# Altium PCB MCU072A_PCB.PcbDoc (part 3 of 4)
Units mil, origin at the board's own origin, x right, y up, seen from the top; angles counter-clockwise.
Board outline 2661.1 x 1953.35 mil, 8 copper layers (Top Layer, Mid-Layer 2, Mid-Layer 3, Mid-Layer 4, Mid-Layer 5, Mid-Layer 6, Mid-Layer 7, Bottom Layer), stack 61.2 mil thick; 186 components, 165 nets, 716 pads, 419 vias.
Unrouted connection lines stored in the file: 1.
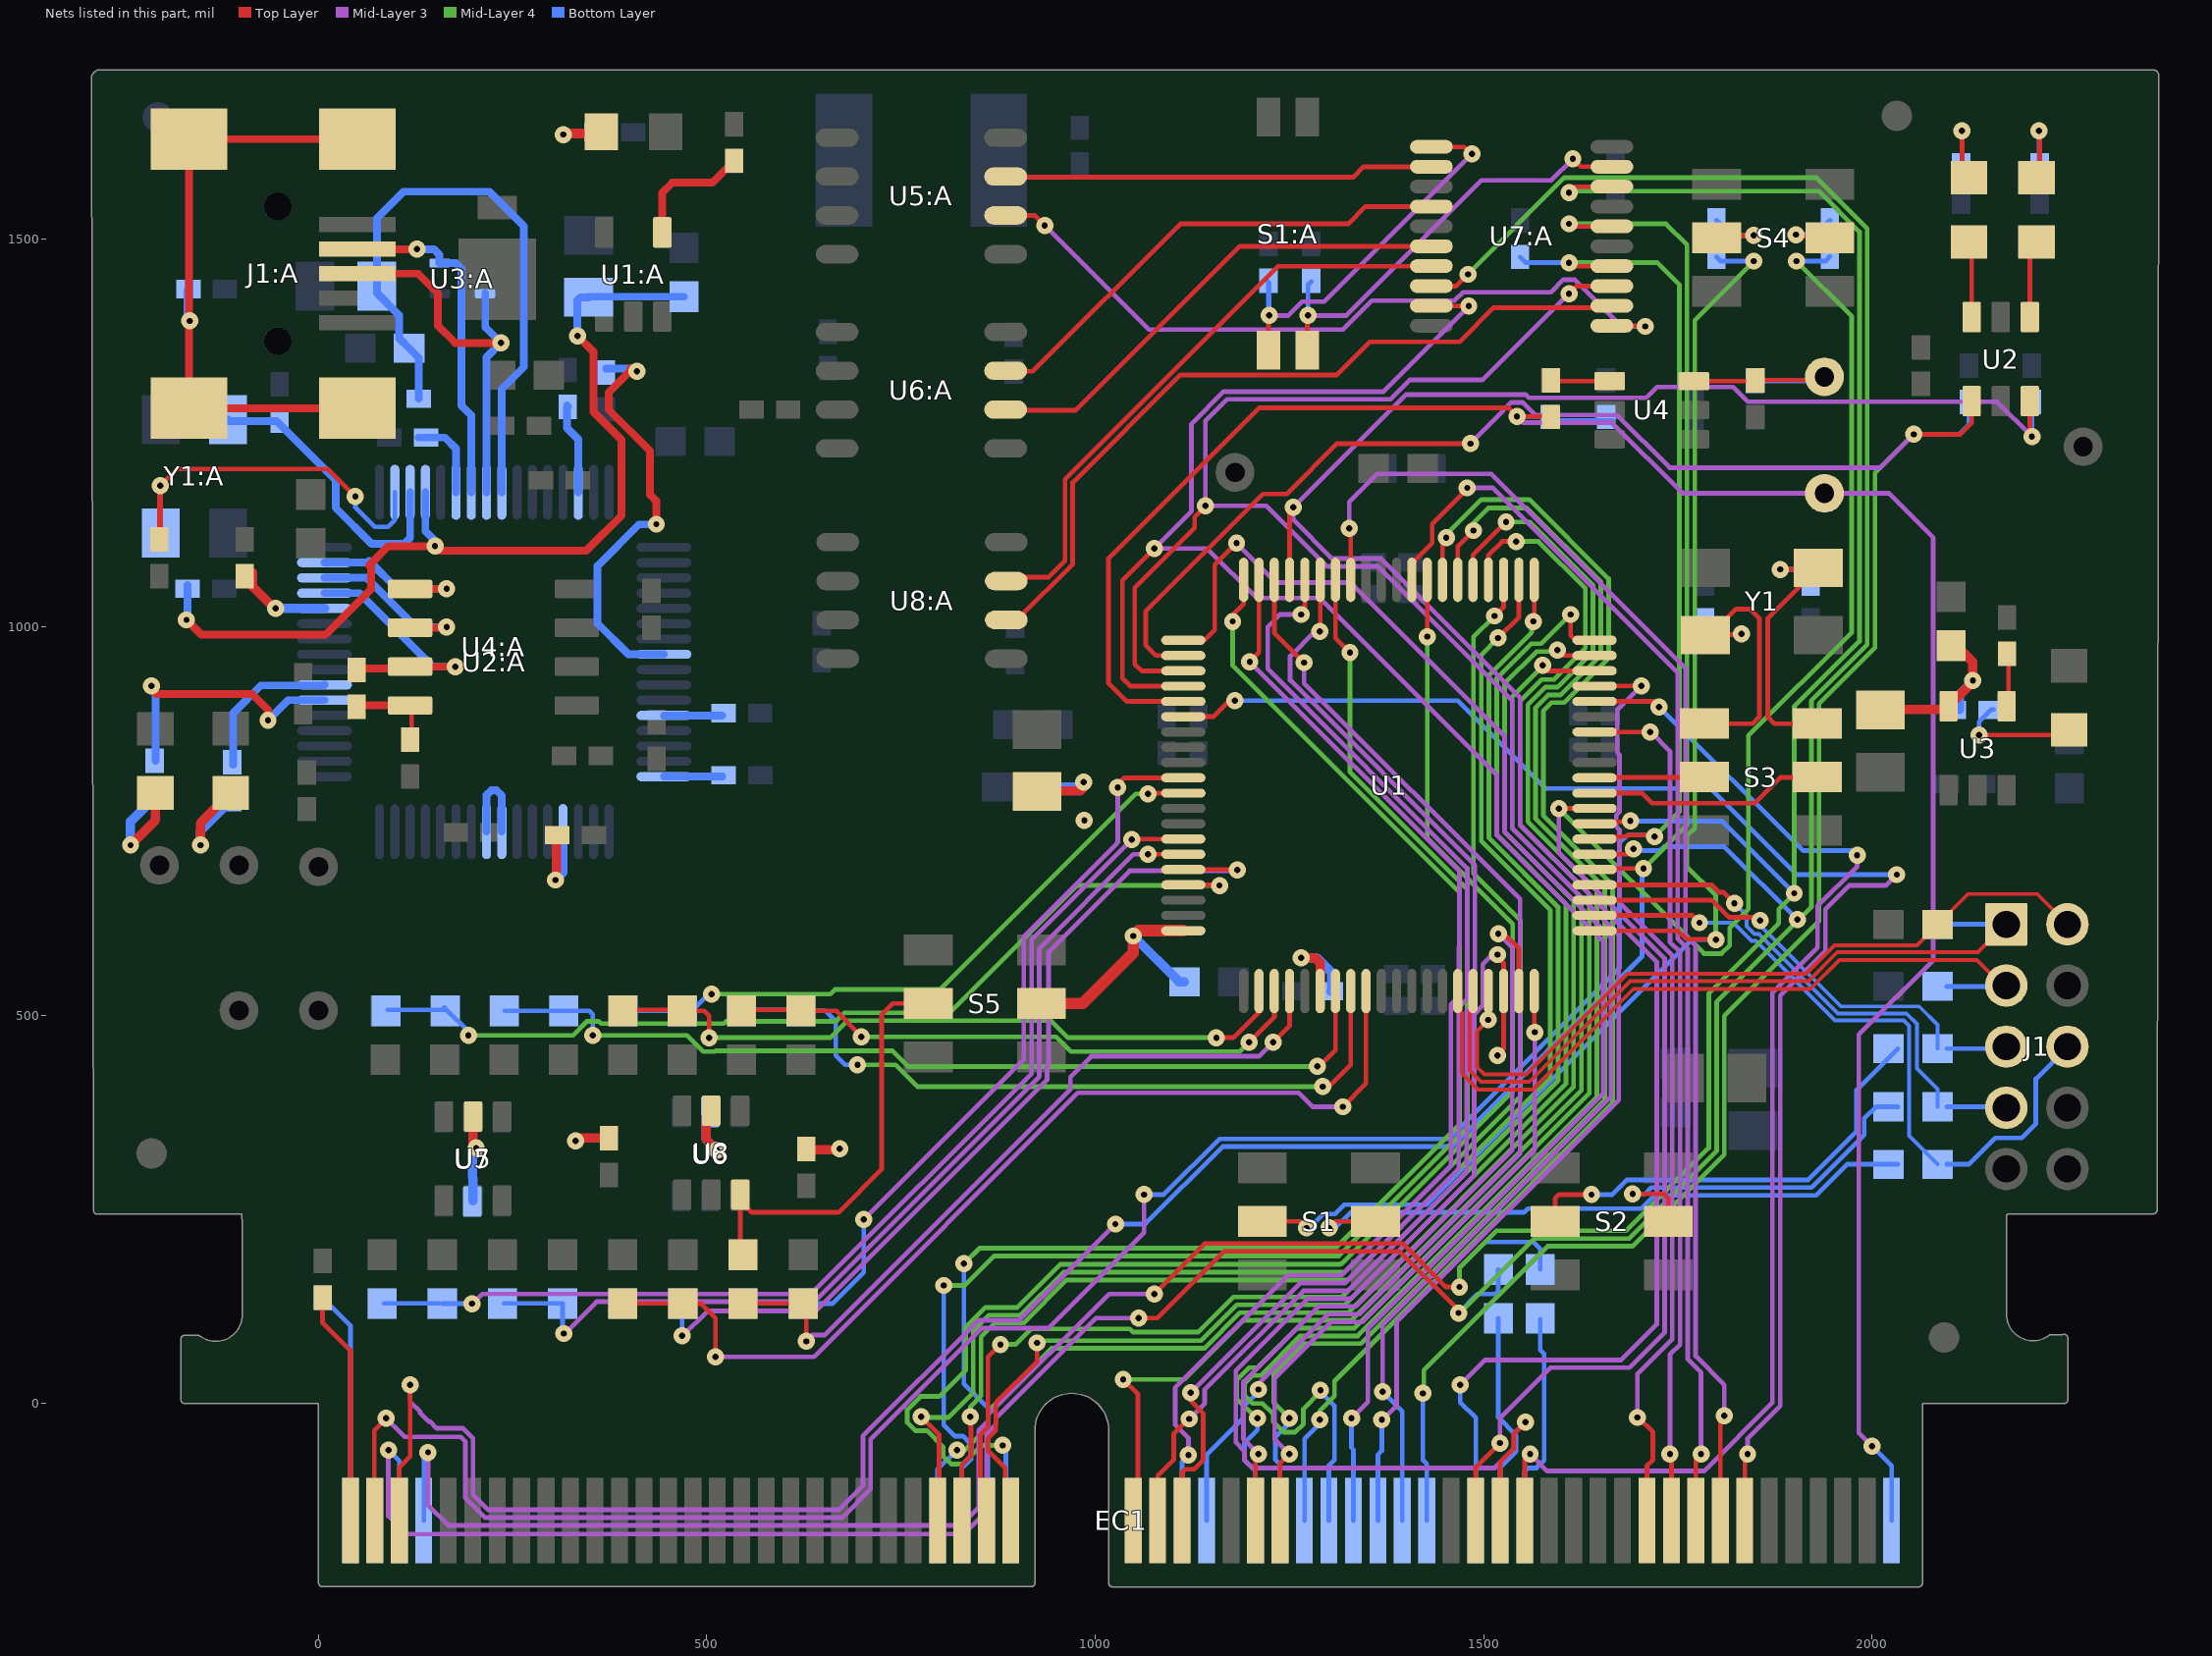
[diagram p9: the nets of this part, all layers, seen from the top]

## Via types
v1: diameter 22, hole 8, Top Layer to Bottom Layer, tented both sides, 419 vias

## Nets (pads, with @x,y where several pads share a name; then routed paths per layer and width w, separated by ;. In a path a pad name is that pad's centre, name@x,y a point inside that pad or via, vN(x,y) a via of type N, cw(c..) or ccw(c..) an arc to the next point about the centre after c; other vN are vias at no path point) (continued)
MCU_A4/C14: C33.1 R27.1 U1.27 | length 1200.8
  Top Layer w6: v1(1286,434) 1288.5,434 1309.31,454.81 U1.27@1309.31,531
  Mid-Layer 4 w6: v1(353,474) 474.54,474 495.54,453 510.46,453 511.46,454 739.14,454 759.14,434 v1(1286,434)
  Bottom Layer w6: R27.1@239.57,505.5 C33.1@315.86,505.5 348.5,505.5 353,501 v1(353,474)
MCU_A5/C2: C34.1 R28.1 U1.17 | length 1221
  Top Layer w6: U1.17@1113.45,667.81 1159.19,667.81 v1(1160,667)
  Mid-Layer 4 w6: v1(193,474) 327.54,474 345.54,492 360.72,492 363.72,489 517.74,489 521.74,489 524.74,492 666.14,492 677.14,503 812.43,503 976.43,667 v1(1160,667)
  Bottom Layer w6: C34.1@89.1,506.9 163.9,506.9 R28.1@164.4,507.4 ; R28.1@162,509.79 R28.1@164.4,507.4 ; R28.1@164.79,507 R28.1@164.4,507.4 ; v1(193,474) 193,478.79 R28.1@164.4,507.4
MCU_A6: C35.1 R29.1 U1.10 | length 1030.8
  Top Layer w6: v1(1029,793) 1029,795 1028,796 1026,794 1037.61,805.61 U1.10@1113.45,805.61
  Mid-Layer 3 w6: v1(702,237) 908,443 908,601.32 1026,719.32 1029,722.32 v1(1029,793)
  Bottom Layer w6: R29.1@539.1,128.9 C35.1@617.1,128.9 ; C35.1@623.93,128.5 661.5,128.5 702,169 v1(702,237)
MCU_A7/C3: C36.1 R30.1 U1.23 | length 759.8
  Top Layer w6: R30.1@539.1,506.9 C36.1@615.1,506.9 ; C36.1@621,505.5 666.5,505.5 699,472.99 v1(699,472) ; v1(1198,465) 1230.57,497.57 U1.23@1230.57,531
  Mid-Layer 4 w6: v1(699,472) 949.86,472 968.86,453 1186,453 v1(1198,465)
MCU_A8/C11: C37.1 R31.1 U1.24 | length 983.2
  Top Layer w6: R31.1@539.1,128.9 C37.1@616.9,128.9 ; C37.1@624,128.5 624.5,129 627.5,126 625,123.5 626,122.5 624,120.5 628,116.5 v1(628,80) ; v1(1229,465) 1229,462 1230,463 1230,466 1250.26,486.26 U1.24@1250.26,531
  Mid-Layer 3 w6: v1(628,80) 636,88 651.71,88 968,404.29 968,420.05 994.95,447 1211,447 v1(1229,465)
MCU_A9/C8: C38.1 R32.1 U1.28 | length 958.6
  Top Layer w6: v1(1293,408) 1301,408 1329,436 U1.28@1329,531
  Mid-Layer 4 w6: v1(694,436) 743,436 771,408 v1(1293,408)
  Bottom Layer w6: R32.1@539.1,506.9 C38.1@616.9,506.9 ; C38.1@621,505.5 652.5,505.5 666,492 666,448 678,436 v1(694,436)
MCU_A10/C10: C39.1 R33.1 U1.29 | length 1296
  Top Layer w6: C39.1@389.1,128.9 R33.1@458,128.9 ; R33.1@458,128.5 R33.1@469.08,128.5 492.56,128.5 511,110.06 v1(511,60) ; v1(1318.75,382) 1348.69,411.94 U1.29@1348.69,531
  Mid-Layer 3 w6: v1@512,60 637.85,60 977.85,400 1262,400 1280,382 v1(1318.75,382)
MCU_A11/C0: C40.1 R34.1 U1.16 | length 1250.7
  Top Layer w6: U1.16@1113.45,687.5 1182.5,687.5 v1(1183,687)
  Mid-Layer 3 w6: v1@469,87 501,119 640.28,119 938,416.72 938,433.89 940,435.89 940,581.72 1044.28,686 1182,686 v1(1183,687)
  Bottom Layer w6: C40.1@389.1,128.9 464.1,128.9 R34.1@466.79,126.21 ; R34.1@465.1,128.9 468,126 v1(468,87)
  Bottom Layer w12: R34.1@464.1,128.9 R34.1@465.1,128.9
MCU_A12/C1: C41.1 R35.1 U1.22 | length 907.2
  Top Layer w6: C41.1@389.1,506.9 R35.1@463.9,506.9 ; R35.1@468.14,505.5 496.5,505.5 503,499 v1(503,471) ; v1(1156,471) 1178,471 1210.89,503.89 U1.22@1210.89,531
  Mid-Layer 4 w6: v1(503,471) 659.28,471 681.28,493 943,493 965,471 v1(1156,471)
MCU_A14/C4: C42.1 R36.1 U1.15 | length 1272.6
  Top Layer w6: v1@1064,707.18 v1(1067.92,707.18) U1.15@1113.45,707.18
  Mid-Layer 3 w6: v1@317,90 358,131 638.14,131 928,420.86 928,586 1049.18,707.18 v1(1067.92,707.18)
  Bottom Layer w6: R36.1@239.1,128.9 C42.1@313.1,128.9 ; v1@314.1,83.1 C42.1@314.1,128.9
  other v1: 316,90
MCU_A15/C7: C43.1 R37.1 U1.14 | length 1372.7
  Top Layer w6: v1(1047,726.18) 1047.69,726.87 U1.14@1113.45,726.87
  Mid-Layer 3 w6: v1@198.5,128.5 211,141 634,141 918,425 918,597.18 v1(1047,726.18)
  Bottom Layer w6: C43.1@84.1,128.9 R37.1@155.1,128.9 ; R37.1@159.5,128.5 v1(197.5,128.5)
MCU_A_3V3: C11.2 C16.1 C26.1 C27.1 L2.2 U1.26 U5.5 U6.5 U7.5 U8.5 | length 553.1
  Top Layer w12: U5.5@199.1,369.53 199.1,334.1 203,330.2 v1(203,329) ; v1@332,338 335.62,341.62 C27.1@376,341.62 ; U8.5@499.1,369.53 499.1,339.9 v1(513,326) ; C26.1@626,326.62 669.62,326.62 v1(671,328) ; L2.2@925,789 981,789 v1@986,794 ; v1(1265,574) 1283.07,574 1289.63,567.44 U1.26@1289.63,531
  Bottom Layer w12: U7.5@199.1,261.27 199.1,290.2 198,291.3 198,329 v1@201,332 ; U6.5@499.1,369.53 499.1,339.9 v1(513,326) ; C11.2@936.5,794 979,794 v1(985,800) ; v1(1265,574) 1285,574 1304,555 1304,531.38 C16.1@1303.62,531
  other v1: 331,338 986,751
MCU_C6: C44.1 R38.1 U1.11 | length 837.1
  Top Layer w6: v1@1067.92,785.92 U1.11@1113.45,785.92
  Mid-Layer 4 w6: v1(506,527) 658.72,527 664.72,533 800,533 1052,785 v1(1067.92,785)
  Bottom Layer w6: C44.1@392.14,505.5 R38.1@468.43,505.5 480.5,505.5 502,527 v1(506,527)
MCU_GPIO0: EC1.49 U1.63 | length 1842.1
  Top Layer w6: v1@775,-17 v1@775.5,-17.5 ; v1(776,-17) 799,-40 799,-150.67 EC1.49@796.97,-150.67 ; v1(1514,1014) 1525.85,1025.85 U1.63@1525.85,1060.53
  Mid-Layer 4 w6: v1(776,-17) 777,-18 811.14,-18 843.07,13.93 843.07,93.53 863.17,113.63 903.77,113.63 959.14,169 1321,169 1547.66,395.66 1547.66,621.77 1487,682.43 1487,987 v1(1514,1014)
MCU_GPIO1: EC1.51 U1.62 | length 1816.6
  Top Layer w6: EC1.51@828.46,-150.67 828.46,-78.99 840,-67.46 840,-18 v1(839,-17) ; v1(1518.69,985.69) 1545.54,1012.54 U1.62@1545.54,1060.53
  Mid-Layer 4 w6: v1(839,-17) 839,-4.28 853.07,9.79 853.07,86.07 870.63,103.63 907.91,103.63 963.28,159 1325.14,159 1586,419.86 1586,635 1497,724 1497,964 v1(1518.69,985.69)
MCU_GPIO2: EC1.53 U1.61 | length 1809.7
  Top Layer w6: EC1.53@859.96,-150.67 852,-142.71 852,-40.46 862,-30.46 862,60 v1(878,76) ; v1(1564,1007) 1565.22,1008.22 U1.61@1565.22,1060.53
  Mid-Layer 4 w6: v1(878,76) 897.54,76 917.54,96 1044.54,96 1048.54,92 1133.12,92 1178.12,137 1317.28,137 1596,415.72 1596,639.14 1507,728.14 1507,938.14 1562,993.14 1562,1007 v1(1564,1007)
MCU_GPIO3: EC1.55 U1.60 | length 1824.2
  Top Layer w6: EC1.55@884,-143.21 884,-83 862,-61 862,-44.6 872,-34.6 872,1 925,54 v1(925,78) ; v1(1612,1016) 1612,989.36 1618.59,982.77 U1.60@1642.98,982.77
  Mid-Layer 4 w6: v1(925,78) 928,81 1136.26,81 1182.26,127 1321.43,127 1606,411.57 1606,643.28 1517,732.28 1517,934 1561.35,978.35 1574.35,978.35 v1(1612,1016)
MCU_GPIO4: EC1.50 U1.59 | length 1796.9
  Top Layer w6: v1(1595,970) 1595,964.17 1596.09,963.09 U1.59@1642.98,963.09
  Mid-Layer 4 w6: v1(822,-60) 832.46,-60 862,-30.46 862,-10.46 943.46,71 1140.4,71 1186.4,117 1325.57,117 1616,407.43 1616,647.43 1527,736.43 1527,927 1568.35,968.35 1593.35,968.35 v1(1595,970)
  Bottom Layer w6: EC1.50@796.97,-150.67 796.97,-85.03 v1(822,-60)
MCU_GPIO5: EC1.52 U1.74 | length 1861.8
  Top Layer w6: U1.74@1309.31,1060.53 1309.31,985.57 v1(1328,966.89)
  Mid-Layer 4 w6: v1(805,152) 832.07,152 870.07,190 1313.72,190 1479,355.28 1479,662.14 1328,813.14 v1(1328,966.89)
  Bottom Layer w6: v1(805,152) 805,-28 819,-42 829.46,-42 840,-52.54 840,-72 828.46,-83.54 EC1.52@828.46,-150.67
MCU_GPIO6: EC1.54 U1.80 | length 1884.6
  Top Layer w6: v1(1177,1007) 1177,1015.59 1191.2,1029.8 U1.80@1191.2,1060.53
  Mid-Layer 4 w6: v1(831,180) 851,200 1309.57,200 1469,359.43 1469,658 1177,950 v1(1177,1007)
  Bottom Layer w6: v1(831,180) 831,25 862,-6 862,-148.63 EC1.54@859.96,-150.67
MCU_GPIO7: EC1.56 U1.68 | length 1957.6
  Top Layer w6: v1(1427.43,987.43) U1.68@1427.43,1060.53
  Mid-Layer 4 w6: v1(881,-54) 853.46,-54 829.46,-78 814.54,-78 804,-67.46 804,-55.65 783.35,-35 768.54,-35 758,-24.46 758,-8 775,9 799.46,9 833.07,42.62 833.07,97.67 859.03,123.63 899.63,123.63 955,179 1315,179 1316,180 1317.86,180 1489,351.14 1489,353 1537.66,401.66 1537.66,617.63 1427.43,727.86 v1(1427.43,987.43)
  Bottom Layer w6: v1(881,-54) 885,-58 EC1.56@885,-144.21
MCU_GPIO8: EC1.57 U1.58 | length 1597.6
  Top Layer w6: v1(1036,31) 1055,12 EC1.57@1055,-144.61 ; v1(1576,950.35) 1582.94,943.4 U1.58@1642.98,943.4
  Mid-Layer 4 w6: v1(1036,31) 1114.54,31 1190.54,107 1329.71,107 1626,403.29 1626,651.57 1537,740.57 1537,910 1576,949 v1(1576,950.35)
MCU_GPIO9: EC1.59 U1.75 | length 1531.7
  Top Layer w6: EC1.59@1080.43,-150.67 1080.43,-93.02 1101,-72.46 1101,-39 v1@1120,-20 ; v1(1289,994) 1289.63,994.63 U1.75@1289.63,1060.53
  Mid-Layer 3 w6: v1(1121,-20) 1141,0 1141,18 1268,145 1325.28,145 1478,297.72 1478,505.6 1489,516.6 1489,693.28 1251,931.28 1251,962.13 1282.87,994 v1(1289,994)
MCU_GPIO10: EC1.61 U1.76 | length 1559
  Top Layer w6: EC1.61@1111.93,-150.67 1111.93,-88.52 1115.85,-84.6 1127.46,-84.6 1139,-73.06 1139,-12.54 1123,3.46 v1(1123,14) ; v1(1265,1016) 1269.94,1020.94 U1.76@1269.94,1060.53
  Mid-Layer 3 w6: v1(1123,14) 1123,14.14 1263.86,155 1321.14,155 1468,301.86 1468,509.74 1479,520.74 1479,689.14 1222.13,946.01 1222.13,978 1222,978.13 1222,1000 1238,1016 v1(1265,1016)
MCU_GPIO11: J1.2 R5.2 U1.37 | length 980.9
  Top Layer w5: v1(1506,494) 1491.5,479.5 1491.5,432.93 1500.94,423.5 1555.07,423.5 1685.07,553.5 1915.19,553.5 1951.62,589.93 2057.93,589.93 2124,656 2212.69,656 J1.2@2251.84,616.85
  Top Layer w6: v1(1506,494) 1506,530.83 U1.37@1506.17,531
MCU_GPIO12: J1.1 R3.2 U1.36 | length 962.3
  Top Layer w5: U1.36@1486.48,531 1486.48,508.48 1482,504 1482,429 1497,414 1559,414 1689,544 1918.41,544 1955.34,580.93 2136.55,580.93 J1.1@2173.1,617.48
  Bottom Layer w6: R3.2@2096.5,617 2172.62,617 J1.1@2173.1,617.48
MCU_GPIO13: J1.3 R4.2 U1.35 | length 977.8
  Top Layer w5: U1.35@1466.8,531 1466.8,508.2 1472,503 1472,424.86 1492.86,404 1563.14,404 1574.14,415 1693.14,534 1921.14,534 1958.07,570.93 2135,570.93 2167.19,538.74 J1.3@2173.1,538.74
  Bottom Layer w6: R4.2@2096.5,537 2171.36,537 J1.3@2173.1,538.74
MCU_GPIO14: EC1.62 U1.79 | length 1530.4
  Top Layer w6: v1(1199,955) 1210.89,966.89 U1.79@1210.89,1060.53
  Mid-Layer 3 w6: v1(1120,-66.6) 1120,-44.46 1103,-27.46 1103,20 1248,165 1317,165 1458,306 1458,513.88 1468,523.88 1468,587 1469,588 1469,685 v1(1199,955)
  Bottom Layer w6: EC1.62@1111.93,-150.67 1111.93,-74.67 v1(1120,-66.6)
MCU_GPIO15: EC1.64 U1.78 | length 1530
  Top Layer w6: U1.78@1230.57,1060.53 1230.57,992.43 v1(1269,954)
  Mid-Layer 3 w6: v1(1210,18) 1210,25.14 1299.86,115 1340.14,115 1547,321.86 1547,649.43 1269,927.43 v1(1269,954)
  Bottom Layer w6: EC1.64@1143.42,-150.67 1143.42,-66.12 1190,-19.54 1190,-5 v1@1210,15
MCU_GPIO16: EC1.67 U1.39 | length 1033.2
  Top Layer w6: EC1.67@1206.42,-150.67 1206.42,-68.58 v1(1210,-65) ; v1(1519,605) 1526.38,605 1545.54,585.84 U1.39@1545.54,531
  Mid-Layer 3 w6: v1(1210,-65) 1191,-46 1191,28 1288,125 1336,125 1537,326 1537,587 v1(1519,605)
MCU_GPIO17: EC1.69 U1.40 | length 857.2
  Top Layer w6: EC1.69@1237.91,-150.67 1237.91,-77.09 v1(1250,-65) ; U1.40@1565.22,531 1565.22,478.78 v1(1566,478)
  Mid-Layer 3 w6: v1(1250,-65) 1231,-46 1231,32 1304,105 1344.28,105 1566,326.72 v1(1566,478)
MCU_GPIO18: S3.5 U1.50 | length 306.9
  Top Layer w6: U1.50@1642.98,785.92 1643.06,786 1704,786 1717,773 1849,773 1882,806 S3.5@1930.83,806
MCU_GPIO19: S3.2 U1.51 | length 142.4
  Top Layer w6: U1.51@1642.98,805.61 1643.37,806 S3.2@1785.17,806
MCU_GPIO22: EC1.72 U1.67 | length 1789.3
  Top Layer w6: U1.67@1447.11,1060.53 1447.11,1108.11 1453,1114 v1(1452,1115)
  Mid-Layer 4 w6: v1(1289,-21) 1289,-9.46 1308,9.54 1308,28.72 1666,386.72 1666,668.14 1577,757.14 1577,891.8 1587.54,902.35 1603.73,902.35 1661,959.62 1661,1062 1559,1164 1497,1164 1452,1119 v1(1452,1115)
  Bottom Layer w6: EC1.72@1269.41,-150.67 1269.41,-45.59 1289,-26 v1(1289,-21)
MCU_GPIO23: EC1.74 U1.65 | length 1931.8
  Top Layer w6: U1.65@1486.48,1060.53 1486.48,1092.48 v1(1529,1135)
  Mid-Layer 4 w6: v1@1290,15 1268,-7 1268,-26.46 1257.46,-37 1242.54,-37 1229,-23.46 1229,-13.54 1215.46,0 1202.54,0 1192,10.54 1192,25.46 1202.54,36 1213.14,36 1264.14,87 1337.99,87 1646,395.01 1646,659.85 1557,748.85 1557,900.09 1579.26,922.35 1594.94,922.35 1641,968.4 1641,1053.72 1559.72,1135 v1(1529,1135)
  Bottom Layer w6: v1@1290,15 1308,-3 1308,-72.46 1300.9,-79.55 EC1.74@1300.9,-150.67
  other v1: 1290,17
MCU_GPIO24: R17.2 S1.2 U1.41 | length 1871
  Top Layer w6: S1.2@1215.27,234.46 1263.54,234.46 v1(1272,226) ; U1.41@1642.98,608.76 1750.01,608.76 1761,597.76 1798.5,597.76 v1(1799,597.26)
  Mid-Layer 4 w6: v1(1799,597.26) 1799,654.04 1761.5,691.54 1761.5,730.36 1772,740.86 1772,1395 v1(1848,1471)
  Bottom Layer w6: 1283,225.46 1283,233.46 1293.54,244 1308.46,244 1320.46,256 1427,256 1768.26,597.26 v1(1799,597.26) ; R17.2@1800,1476.38 1805.38,1471 v1(1848,1471)
MCU_GPIO25: J1.6 R7.2 U1.42 | length 910.9
  Top Layer w6: U1.42@1642.98,628.44 1768.56,628.44 v1(1778,619) v1@1779,618
  Bottom Layer w5: v1(1778,619) 1821.67,619 1845.17,595.5 1850.5,595.5 1952.7,493.3 2040.7,493.3 2047.81,486.19 2047.81,344.69 R7.2@2084.5,308
  Bottom Layer w6: R7.2@2096.5,308 2125,308 2159,342 2193,342 2211,360 2211,418 2251.84,458.84 J1.6@2251.84,459.37
MCU_GPIO26: J1.5 R6.2 U1.43 | length 620.4
  Top Layer w6: U1.43@1642.98,648.13 1793.42,648.13 1815.54,626 1852.14,626 v1(1856.14,622)
  Bottom Layer w5: v1(1856.14,622) 1856.14,615.31 1960.16,511.3 2048.84,511.3 2060.84,511.3 2084.5,487.65 2084.5,469 R6.2@2084.5,457
  Bottom Layer w6: R6.2@2096.5,457 2170.1,457 J1.5@2173.1,460
MCU_GPIO27: J1.7 R10.2 U1.44 | length 691.9
  Top Layer w6: U1.44@1642.98,667.81 1793.73,667.81 1803.42,658.13 1809.14,658.13 1823,644.27 v1(1823,644)
  Bottom Layer w5: v1(1823,644) 1838.64,628.36 1838.64,614.75 1848.89,604.5 1854.23,604.5 1956.43,502.3 2044.43,502.3 2057.81,488.92 2057.81,431.3 2084.5,404.61 R10.2@2084.5,382 ; J1.7@2172.36,382 J1.7@2173.1,381.26
  Bottom Layer w6: R10.2@2096.5,382 J1.7@2172.36,382
MCU_GPIO28: EC1.76 U1.4 U7:A.9 | length 2636
  Top Layer w6: v1(1076,1101) 1035,1060 1035,933.72 1038.04,930.67 1045,923.72 U1.4@1113.45,923.72 ; U7:A.9@1430.05,1413.27 v1@1479.27,1413.27 ; v1(1481,1413) 1479.55,1413 v1@1479.27,1413.27 ; v1@1483,1414 1482.27,1413.27 v1@1479.27,1413.27
  Mid-Layer 3 w6: v1(1330,-19) 1351,2 1351,96 1654,399 1654,595.43 1575.43,674 1575,674 1517,732 1517,809 1289,1037 1208,1037 1144,1101 v1(1076,1101) 1124,1149 1124,1261.6 1165.4,1303 1371,1303 v1(1481,1413)
  Bottom Layer w6: v1(1330,-19) 1330,-57 1332.4,-59.4 EC1.76@1332.4,-150.67
MCU_GPIO29: EC1.78 U1.3 U7:A.13 | length 2746.6
  Top Layer w6: U1.3@1113.45,943.4 1059.6,943.4 1051,952 1051,1050.54 1128,1127.54 1128,1141.42 1141.88,1155.3 v1@1141.88,1156 ; v1(1610,1429) 1619.87,1438.87 U7:A.13@1662.34,1438.87
  Mid-Layer 3 w6: v1(1369,-21) 1370,-21 1388,-3 1388,104.72 1674,390.72 1674,603.72 1537,740.72 1537,904.86 1363.86,1078 1298,1078 1220,1156 v1(1142,1156) 1142,1265.46 1169.54,1293 1379.86,1293 1404.86,1318 1498.4,1318 1609.4,1429 v1(1610,1429)
  Bottom Layer w6: EC1.78@1363.9,-150.67 1363.9,-66.1 1369,-61 v1@1369,-24
MCU_GPIO30: EC1.80 U1.1 | length 1816.6
  Top Layer w6: U1.1@1113.45,982.77 1140.77,982.77 1154,996 1154,1080 v1(1182,1108)
  Mid-Layer 3 w6: v1(1182,1108) 1233,1057 1329.23,1057 1527,859.23 1527,736.57 1664,599.57 1664,394.86 1370,100.86 v1(1370,15)
  Bottom Layer w6: v1(1370,15) 1395.39,-10.39 EC1.80@1395.39,-150.67
MCU_GPIO31: EC1.82 R13.1 U1.2 U2.1 | length 3207
  Top Layer w6: U1.2@1113.45,963.09 1078.22,963.09 1065,976.3 1065,1020 1216,1171 1246.54,1171 1311.54,1236 v1(1483,1236) ; v1(2054,1248) 2114,1248 2128.5,1262.5 U2.1@2128.5,1290.73
  Mid-Layer 3 w6: v1@1475.46,1236 v1(1483,1236) 1525,1278 1525,1278.46 1535.54,1289 1550.46,1289 1566.46,1273 1671.54,1273 1739.54,1205 2011,1205 v1(2054,1248)
  Mid-Layer 4 w6: v1@1423,12 1423,43 1582.38,202.38 1691.66,202.38 1810,320.72 1810,499 1932,621 1932,901 2004,973 2004,1198 v1(2054,1248)
  Bottom Layer w6: v1(1422,13) 1422,-73 1426.89,-77.89 EC1.82@1426.89,-150.67 ; v1(2054,1248) 2113,1248 2125,1260 R13.1@2125,1289.38 R13.1@2125,1296.76
MCU_GPIO32: EC1.85 R18.1 U1.49 | length 2502.4
  Top Layer w6: EC1.85@1489.88,-150.67 1489.88,-82.12 v1(1521,-51) ; v1(1597,766) 1597.24,766.24 U1.49@1642.98,766.24
  Mid-Layer 3 w6: v1(1521,-51) 1521,-19 1586,46 1688,46 1733,91 1733,573 1597,709 v1(1597,766)
  Mid-Layer 4 w6: v1(1597,766) 1783.74,579.26 1806.46,579.26 1817,589.81 1817,612.54 1841,636.54 1841,860 1974,993 1974,1400 v1(1903,1471)
  Bottom Layer w6: v1(1903,1471) 1940,1471 R18.1@1946,1477
MCU_GPIO33: EC1.87 U1.38 | length 1518
  Top Layer w6: v1(1518,448) 1517,448 1525.85,456.85 U1.38@1525.85,531 1525.85,567.15 1515,578 v1(1518,578) ; EC1.87@1521.38,-150.67 1521.38,-76.08 1539,-58.46 1539,-39 v1(1554,-24)
  Mid-Layer 3 w6: v1@1518,584.43 1499,565.43 1499,512.46 1488,501.46 1488,293.57 1329.43,135 1274,135 1181,42 1181,-50.14 1192,-61.14 1192,-72.46 1202.54,-83 1514.46,-83 1539,-58.46 1539,-39 v1(1554,-24)
MCU_GPIO34: EC1.86 R14.1 U1.77 U2.3 | length 2976.6
  Top Layer w6: U1.77@1250.26,1060.53 1250.26,1149.26 v1(1255,1154) ; 2203.31,1255.69 U2.3@2203.31,1290.73
  Mid-Layer 3 w6: v1@1469,24 v1@1469.5,24.5 ; v1(1470,24) 1502,56 1677,56 1723,102 1723,568.86 1547,744.86 1547,909 1368,1088 1305,1088 1255,1138 v1(1255,1154) 1400,1299 1554.6,1299 1558.6,1295 1709.46,1295 1723.46,1309 1821.46,1309 1840.46,1290 2161,1290 v1(2206,1245)
  Bottom Layer w6: v1(1470,24) 1470,1.46 1490,-18.54 1490,-147.21 1486.42,-147.21 EC1.86@1489.88,-150.67 ; v1(2206,1245) R14.1@2206,1289.38
MCU_GPIO35/TDI: EC1.8 R9.1 U1.48 U7:A.18 | length 4340
  Top Layer w6: v1(1076,141) 1141,206 1395.72,206 1451.72,150 v1(1469,150) ; v1(1610,1559) 1617.82,1566.82 U7:A.18@1662.34,1566.82 ; U1.48@1642.98,746.55 1645.43,749 1697,749 1696,750 v1(1689,750)
  Mid-Layer 3 w6: v1(141,-63) 141,-131 167,-157 827,-157 850,-134 850,-34.86 862,-22.86 862,-14.86 1017.86,141 v1(1076,141)
  Mid-Layer 4 w6: v1(1469,150) 1469,175 1516.38,222.38 1683.38,222.38 1790,329 1790,528 1880,618 1880,636.28 v1@1900.36,656.64 ; v1(1610,1559) 1612,1561 1931.86,1561 1984,1508.86 1984,981.28 1900,897.28 v1(1900,657)
  Bottom Layer w6: EC1.8@135.55,-150.67 135.55,-68.45 v1@140.55,-63.45 ; v1(1469,150) 1469,175 1502,208 1563.98,208 1573,198.98 R9.1@1573,172.5 ; v1(1689,750) 1807,750 v1(1900,657)
MCU_GPIO37/TDO: EC1.6 R8.1 U1.46 U7:A.8 | length 4550.2
  Top Layer w6: v1(1056,110) 1080,110 1166,196 1391.58,196 1467.77,119.82 v1(1467.77,116.5) ; U7:A.8@1430.05,1438.87 1464.87,1438.87 v1(1480,1454) ; U1.46@1642.98,707.18 1686.18,707.18 v1(1693,714)
  Mid-Layer 3 w6: v1(90,-60) 90,-145 113,-168 831,-168 859.73,-139.27 859.73,-138.41 860,-138.14 860,-39 872,-27 872,-19 1001,110 v1(1056,110)
  Mid-Layer 4 w6: v1(1467.77,116.5) 1469.35,116.5 1565.23,212.38 1687.52,212.38 1800,324.86 1800,517 1922,639 1922,905.14 1994,977.14 1994,1513 1928.43,1578.57 1604.12,1578.57 1480,1454.46 v1(1480,1454)
  Bottom Layer w6: v1(90,-60) 104.05,-74.05 EC1.6@104.05,-150.67 ; v1(1467.77,116.5) 1492.26,141 1515,141 1519,145 R8.1@1519,172.5 ; v1(1693,714) 1695,712 1727.46,712 1732.46,717 1810,717 v1(1904,623)
MCU_GPIO39: EC1.89 U1.56 | length 1620.1
  Top Layer w6: EC1.89@1552.87,-150.67 1552.87,-72.13 v1(1560,-65) ; U1.56@1642.98,904.03 1718.97,904.03 v1(1726,897)
  Mid-Layer 3 w6: v1(1560,-65) 1582,-87 1784,-87 1872,1 1872,529.14 1930,587.14 1930,640.6 1981,691.6 v1@1981,712
  Bottom Layer w6: v1(1726,897) 1911,712 1926.31,712 1926.51,711.8 1934.8,711.8 1935,712 v1@1981,712
  other v1: 1981,706
MCU_GPIO40: EC1.68 U1.64 | length 1732.6
  Top Layer w6: U1.64@1506.17,1060.53 1506.17,1092.17 1524,1110 v1(1542,1110)
  Mid-Layer 4 w6: v1(1209,-19) 1207.4,-19 1182,6.4 1182,29.6 1198.4,46 1209,46 1260,97 1333.85,97 1636,399.15 1636,655.71 1547,744.71 1547,904.23 1575.12,932.35 1590.8,932.35 1631,972.54 1631,1049.57 1570.57,1110 v1(1542,1110)
  Bottom Layer w6: EC1.68@1206.42,-150.67 1206.42,-86.87 1192,-72.46 1192,-51 1209,-34 v1(1209,-19)
MCU_GPIO41: EC1.70 U1.66 | length 1820.7
  Top Layer w6: U1.66@1466.8,1060.53 1466.8,1103.8 v1(1487,1124)
  Mid-Layer 4 w6: v1(1250,-19) 1230,1 1230,38.72 1268.28,77 1342.14,77 1656,390.86 1656,663.99 1567,752.99 1567,895.94 1583.4,912.35 1599.58,912.35 1651,963.76 1651,1057.86 1555.86,1153 1506,1153 1487,1134 v1(1487,1124)
  Bottom Layer w6: EC1.70@1237.91,-150.67 1237.91,-78.37 1232,-72.46 1232,-43 1250,-25 v1(1250,-19)
MCU_GPIO42: EC1.99 U1.57 | length 1211.1
  Top Layer w6: U1.57@1642.98,923.72 1643.26,924 v1(1703,924) ; v1(1698,-18) 1699,-18 1718,-37 1718,-72.46 1710.35,-80.1 EC1.99@1710.35,-150.67
  Mid-Layer 3 w6: v1(1698,-18) 1698,37.64 1743,82.64 1743,577.14 1675,645.14 1675,738.54 1671,742.54 1671,757.46 1675,761.46 1675,835.54 1672,838.54 1672,893 v1(1703,924)
MCU_GPIO43: EC1.101 U1.54 | length 1109.2
  Top Layer w6: U1.54@1642.98,864.66 v1(1714.66,864.66) ; v1(1740,-65) 1741.85,-66.85 EC1.101@1741.85,-150.67
  Mid-Layer 3 w6: v1@1715,865 1740,840 1740,594.28 1753,581.28 1753,75.86 1740,62.86 v1(1740,-65)
MCU_GPIO44: EC1.103 U1.69 | length 1622.1
  Top Layer w6: U1.69@1407.74,1060.53 1407.74,1081.73 1434,1107.99 1434,1132.54 1479,1177.54 v1(1479,1179) ; EC1.103@1773.35,-150.67 1773.35,-71.65 v1@1778.35,-66.65
  Mid-Layer 3 w6: v1(1479,1179) 1512,1179 1750,941 1750,598.43 1763,585.43 1763,56.86 1780,39.86 v1(1780,-65)
MCU_GPIO45: EC1.105 U1.73 | length 1773.3
  Top Layer w6: v1(1327,1127) 1329,1125 U1.73@1329,1060.53 ; EC1.105@1804.84,-150.67 1804.84,-21.16 v1(1810,-16)
  Mid-Layer 3 w6: v1(1327,1127) 1327,1161 1363,1197 1510,1197 1760,947 1760,602.57 1773,589.57 1773,61 1810,24 v1(1810,-16)
MCU_GPIO46: EC1.107 U1.6 | length 1960.4
  Top Layer w6: U1.6@1113.45,884.35 1152.27,884.35 1172.92,905 v1(1180,905) ; EC1.107@1836.34,-150.67 1836.34,-68.66 v1(1840,-65)
  Mid-Layer 3 w6: v1(1840,-65) 1840,-45.14 1882,-3.14 1882,525 1940,583 1940,636.46 1970.54,667 2018,667 v1(2032,681)
  Bottom Layer w6: v1(1180,905) 1467,905 1580,792 1792,792 1903,681 v1(2032,681)
MCU_TCK: EC1.5 U1.45 U7:A.16 | length 3444
  Top Layer w6: EC1.5@104.05,-150.67 104.05,-81.95 118,-68 v1(118,24) ; v1(1610,1519) 1613.36,1515.64 U7:A.16@1662.34,1515.64 ; U1.45@1642.98,687.5 1642.98,689 v1(1706,689)
  Mid-Layer 3 w6: v1(118,24) 118,2 131,-11 131,-12.46 141.54,-23 143,-23 152,-32 186.14,-32 199,-44.86 199,-117.46 218.54,-137 670,-137 701,-106 701,-42 850,107 902,107 v1(1026,231)
  Mid-Layer 4 w6: v1(1610,1519) 1735,1519 1762,1492 1762,745 v1(1706,689)
  Bottom Layer w6: v1(1026,231) 1064.39,231 1164.14,330.75 1459.32,330.75 1704,575.43 1704,687 v1(1706,689)
MCU_TMS: EC1.3 R22.1 U1.47 U7:A.14 | length 3466.1
  Top Layer w6: EC1.3@72.56,-150.67 72,-150.11 72,-35 v1@88,-19 ; v1(1610,1469) 1614.54,1464.46 U7:A.14@1662.34,1464.46 ; U1.47@1646.11,730 1683.54,730 1685.54,732 1718,732 v1(1720,730)
  Mid-Layer 3 w6: v1(87,-19) 111,-43 183,-43 189,-49 189,-121.6 214.4,-147 674.14,-147 711,-110.14 711,-46.14 854.14,97 940,97 1063,220 v1(1063,269)
  Mid-Layer 4 w6: v1(1610,1469) 1724,1469 1752,1441 1752,762 v1(1720,730)
  Bottom Layer w6: v1(1063,269) 1088.25,269 1160,340.75 1455.18,340.75 1675,560.57 1675,721.46 1685.54,732 1718,732 v1(1720,730) ; R22.1@1547,1476.38 1554.38,1469 v1(1610,1469)
MCU_VREFHI: C28.2 S5.2 U1.20 | length 324.8
  Top Layer w15: S5.2@930.83,515 984,515 1049,580 v1(1049,602) 1055.76,608.76 U1.20@1113.45,608.76
  Bottom Layer w12: v1(1049,602) 1108,543 C28.2@1115,543
MCU_XRSN: C23.2 EC1.120 R19.1 R20.2 TP5.1 U1.5 | length 2965.4
  Top Layer w6: U1.5@1113.45,904.03 1040.97,904.03 1017,928 1017,1088 1211.13,1282.13 1531.87,1282.13 v1(1543,1271) 1584.38,1271 1585.38,1272 R20.2@1587,1270.38
  Mid-Layer 3 w6: v1(1543,1271) 1551,1263 1665.46,1263 1756.32,1172.13 2021.87,1172.13 2079,1115 2079,571 1983,475 1983,-38 v1(2000,-55)
  Bottom Layer w6: v1(1543,1271) 1584.38,1271 R19.1@1585,1270.38 ; R19.1@1589.52,1265.48 C23.2@1666.6,1265.48 ; v1(2000,-55) 2025.31,-80.31 EC1.120@2025.31,-150.67
MID_A8/C11: R31.2 S5.5 U8.3 | length 551.7
  Top Layer w6: R31.2@541,195.5 543.04,197.54 U8.3@543.04,261.09 ; U8.3@542.11,262.03 U8.3@543.04,261.09 ; U8.3@543.04,268.73 U8.3@543.04,261.09 ; S5.5@785.17,515 739.5,515 725,500.5 725,301.54 669.46,246 558.13,246 U8.3@543.04,261.09
MID_SCI-RX: U5:A.6 U7:A.11 | length 979.9
  Top Layer w6: U5:A.6@883.5,1529.87 922.13,1529.87 v1(935,1517) ; U7:A.11@1665.14,1387.84 1707.16,1387.84 v1(1708,1387)
  Mid-Layer 3 w6: v1(935,1517) 1069,1383 1319.14,1383 1356.14,1420 1462.54,1420 1473.54,1431 1586.54,1431 1602.54,1447 1617.46,1447 1677.46,1387 v1(1708,1387)
MID_SCI-TX: U7:A.7 U8:A.3 | length 772.4
  Top Layer w6: U8:A.3@885,1064 940,1064 961,1085 961,1190 1235.46,1464.46 U7:A.7@1430.05,1464.46
MID_TCK: U6:A.7 U7:A.4 | length 630.5
  Top Layer w6: U6:A.7@890,1329 919.54,1329 1109.54,1519 1325.54,1519 1347.77,1541.23 U7:A.4@1430.05,1541.23
  Top Layer w12: U7:A.4@1428.28,1543 U7:A.4@1430.05,1541.23
MID_TDI: U5:A.7 U7:A.2 | length 554.7
  Top Layer w6: U5:A.7@885,1579 1332.13,1579 1345.54,1592.41 U7:A.2@1430.05,1592.41
  Top Layer w12: U5:A.7@883.5,1579.87 U5:A.7@886.37,1577
MID_TDO: U7:A.12 U8:A.2 | length 1011.7
  Top Layer w6: U8:A.2@883.5,1009.87 900.01,1009.87 971,1080.86 971,1185.86 1109.54,1324.4 1311,1324.4 1353.6,1367 1469,1367 1513,1411 1665.14,1411 U7:A.12@1665.14,1413.43
MID_TMS: U6:A.6 U7:A.6 | length 647.3
  Top Layer w6: U6:A.6@890,1279 975,1279 1186.05,1490.05 1430.05,1490.05 U7:A.6@1449.88,1490.05
NetC4:A_2: C4:A.2 U1:A.4 | length 160.7
  Top Layer w10: U1:A.4@442.6,1507.98 442.6,1559.08 455.41,1571.9 506.87,1571.9 C4:A.2@535.2,1600.22
NetC13:A_1: C13:A.1 C14:A.2 L1:A.1 U2:A.4 | length 1219.1
  Top Layer w10: v1(-170,1009) -150.97,989.97 9.2,989.97 67.67,1048.45 67.67,1081.67 ; 65,1079 67.67,1081.67 ; v1(333.44,1374.72) 353.96,1354.2 353.96,1277.04 390,1241 390,1143.38 344.58,1097.97 156.03,1097.97 v1(150,1104) 90,1104 67.67,1081.67
  Bottom Layer w10: v1(-170,1009) -168.43,1010.57 C14:A.2@-168.43,1053.84 ; U2:A.4@137.64,1173.37 137.64,1123.36 150,1111 v1(150,1104) ; v1(333.44,1374.72) 333.44,1420.22 337.51,1424.29 L1:A.1@347.57,1424.29 348.43,1425.15 C13:A.1@470.54,1425.15
NetC15:A_1: C15:A.1 C16:A.2 L2:A.1 U2:A.9 | length 830.8
  Bottom Layer w10: C16:A.2@128.82,1293.84 128.82,1346.72 C15:A.1@116.69,1358.84 103.85,1371.68 103.85,1401.29 75.2,1429.95 L2:A.1@75.2,1438.84 75.2,1526.28 109.33,1560.42 219.93,1560.42 264.51,1515.83 264.51,1334.85 236.06,1306.4 U2:A.9@236.06,1173.37
NetC17:A_2: C17:A.2 U2:A.2 Y1:A.1 | length 578.7
  Top Layer w6: C17:A.2@-204.8,1112.46 v1@-204.8,1180.81 ; C17:A.2@-203.11,1121.01 -203.11,1181.07 v1(-203.82,1181.79) -182.41,1203.2 12.04,1203.2 v1(47.45,1167.78)
  Bottom Layer w6: Y1:A.1@-203.11,1121.01 v1@-203.11,1181.07 ; v1(47.45,1167.78) 47.45,1153.89 72.53,1128.82 89.38,1128.82 98.27,1137.7 U2:A.2@98.27,1173.37
NetC18:A_2: C18:A.2 U2:A.3 Y1:A.3 | length 383.2
  Bottom Layer w10: Y1:A.3@-116.5,1266.68 -115.04,1265.22 -54.22,1265.22 22,1189 22,1153.55 68.46,1107.09 110.36,1107.09 117.95,1114.68 U2:A.3@117.95,1173.37
NetC21_2: C21.2 U3.4 | length 71.4
  Top Layer w6: U3.4@2176,898.76 C21.2@2176,970.14
NetC22_2: C22.2 R15.1 R16.2 U3.5 | length 241.3
  Top Layer w12: R15.1@2011,893.76 U3.5@2096,893.76 ; U3.5@2098.6,897.9 2130,929.3 v1(2130,930.76) 2130,954.76 2106,978.76 C22.2@2106,982.27
  Bottom Layer w12: R16.2@2112.38,893.76 2112.38,912.14 v1@2132,931.76 ; v1@2129,931.76 v1@2131,933.76
NetC24_2: C24.2 R21.1 TP6.1 U4.6 | length 268
  Top Layer w6: U4.6@1770.73,1316.5 1843.5,1316.5 C24.2@1846.6,1313.4 ; C24.2@1846.6,1312.72 C24.2@1846.6,1313.4 ; C24.2@1849,1311 C24.2@1846.6,1313.4 ; C24.2@1850,1317.62 1934.62,1317.62 TP6.1@1939,1322
  Bottom Layer w6: R21.1@1849,1316.62 1924.62,1316.62 TP6.1@1939,1331
NetD1_1: D1.1 U2.6 | length 91.5
  Top Layer w6: U2.6@2128.5,1399 D1.1@2128.5,1490.5
NetD1_2: D1.2 R11.1 | length 99.9
  Top Layer w6: v1(2116,1639) 2116.22,1638.78 D1.2@2116.22,1586.2
  Bottom Layer w6: v1(2116,1639) 2116.35,1638.65 R11.1@2116.35,1592.1
NetD2:A_2: D2:A.2 R1:A.2 | length 132.5
  Top Layer w10: v1(315,1634) 360.68,1634 D2:A.2@364.09,1637.41 ; v1@319.93,1636.91 D2:A.2@357.85,1636.91
  Bottom Layer w10: v1(315,1634) 317.91,1636.91 R1:A.2@357.85,1636.91
NetD2_1: D2.1 U2.4 | length 83.3
  Top Layer w6: U2.4@2203.31,1399 D2.1@2203.31,1482.31
NetD2_2: D2.2 R12.1 | length 89.5
  Top Layer w6: v1(2215,1639) 2215.91,1638.09 D2.2@2215.91,1586.2
  Bottom Layer w6: R12.1@2215.08,1592.61 v1@2215.08,1628.92
NetD3:A_1: D3:A.1 R6:A.2 | length 159.5
  Top Layer w12: v1(-242,719) -209.8,751.2 -209.8,784.2 D3:A.1@-205,789
  Bottom Layer w12: v1(-242,719) -242,749.38 R6:A.2@-211,780.38
NetD3_2: D3.2 R16.1 | length 171.4
  Top Layer w6: v1(2138,860.76) 2247.46,860.76 D3.2@2254,867.3 ; D3.2@2254,869.83 D3.2@2264.1,869.83
  Bottom Layer w6: v1(2138,860.76) 2138,877.76 2154,893.76 R16.1@2157,893.76
NetD4:A_1: D4:A.1 R7:A.2 | length 159.8
  Top Layer w12: v1(-152,719) -152,747.31 D4:A.1@-113.01,786.3
  Bottom Layer w12: v1(-152,719) -152,737.38 R7:A.2@-111,778.38
NetEC1_1: EC1.1 R1.2 | length 301.9
  Top Layer w6: R1.2@5.31,136.38 5.31,103.69 41.06,67.94 EC1.1@41.06,-150.67
NetEC1_2: EC1.2 R2.1 | length 301.4
  Bottom Layer w6: R2.1@5.51,136.03 41.06,100.48 EC1.2@41.06,-150.67
NetEC1_88: EC1.88 R8.2 | length 278.2
  Bottom Layer w6: R8.2@1519,109.5 1519,-18 1542,-41 1542,-62 1521.38,-82.62 EC1.88@1521.38,-150.67
NetEC1_90: EC1.90 R9.2 | length 277.6
  Bottom Layer w6: EC1.90@1552.87,-150.67 1552.87,-88.13 1558,-83 1568.11,-83 1578,-73.11 1578,64 1573,69 R9.2@1573,108.5
NetJ1:A_2: J1:A.2 U2:A.7 U3:A.5 | length 444.4
  Top Layer w10: J1:A.2@49.86,1486.36 v1(126.72,1486.36) v1@126.99,1486.64
  Bottom Layer w10: v1(126.72,1486.36) 148.54,1486.36 155.67,1479.23 155.67,1468.53 176.86,1468.53 184.11,1461.28 184.11,1284.89 196.69,1272.31 U2:A.7@196.69,1173.37
NetJ1:A_3: J1:A.3 U2:A.8 U3:A.3 | length 518.3
  Top Layer w10: J1:A.3@49.86,1454.87 128.22,1454.87 153.93,1429.16 153.93,1387.7 175.99,1365.64 v1(234.99,1365.64)
  Bottom Layer w10: U3:A.3@214.72,1429.16 214.72,1385.91 v1(234.99,1365.64) 216.38,1347.02 U2:A.8@216.38,1173.37
NetJ1:A_6: J1:A.6 J1:A.7 J1:A.8 J1:A.9 R11:A.1 | length 817.5
  Top Layer w10: J1:A.7@49.86,1281.64 J1:A.9@-166.67,1281.64 -166.67,1393.29 v1(-165.99,1393.98) -166.67,1394.66 J1:A.8@-166.67,1628.09 J1:A.6@49.86,1628.09
  Bottom Layer w10: v1@-168.43,1396.42 R11:A.1@-168.43,1433.84
NetR3:A_2: R3:A.2 U2:A.24 | length 550.5
  Top Layer w10: v1@401.66,1332.46 v1@403.34,1330.79 ; v1(410,1329) 400.96,1329 373.47,1301.5 373.47,1279.88 427,1226.34 427,1170.09 435.01,1162.09 v1(435.01,1132.3) v1@434.61,1131.9
  Bottom Layer w10: R3:A.2@370.2,1332.46 v1@401.66,1332.46 ; v1@434.61,1131.9 412.64,1131.9 359.33,1078.59 359.33,1004.3 398.92,964.71 U2:A.24@444.72,964.71
NetR4:A_1: R4:A.1 U2:A.28 | length 74.7
  Bottom Layer w10: U2:A.28@444.72,885.97 R4:A.1@519.45,885.97
NetR5:A_1: R5:A.1 U2:A.32 | length 75.2
  Bottom Layer w10: U2:A.32@444.72,807.23 R5:A.1@519.96,807.23
NetR6:A_1: R6:A.1 U2:A.54 | length 347.2
  Top Layer w10: v1(-215,924) -215,919.64 -208.75,913.39 -85.22,913.39 -65.01,893.18 v1(-65.01,879.64)
  Bottom Layer w10: R6:A.1@-209.8,827.46 -209.8,912.34 ; v1(-65.01,879.64) -38.99,905.65 U2:A.54@7.72,905.65
NetR7:A_1: R7:A.1 U2:A.55 | length 199
  Bottom Layer w10: R7:A.1@-109.8,822.46 -109.8,888.84 -74.01,924.64 7.02,924.64 U2:A.55@7.72,925.34
NetR8:A_2: R8:A.2 R9:A.1 U4:A.4 | length 129
  Top Layer w6: U4:A.4@112.18,893.46 U4:A.4@116.36,897.64 ; U4:A.4@115,899 U4:A.4@116.36,897.64 ; U4:A.4@117.74,899.02 U4:A.4@116.36,897.64 ; R8:A.2@120,852.62 120,894 116.53,897.47 U4:A.4@116.36,897.64
  Top Layer w10: R9:A.1@44.99,899.02 U4:A.4@117.74,899.02
NetR9:A_2: R9:A.2 U2:A.61 U4:A.3 | length 339.5
  Top Layer w10: R9:A.2@44.99,946.26 115.74,946.26 118.12,948.64 v1(175.99,948.64)
  Bottom Layer w10: U2:A.61@7.72,1043.45 52.67,1043.45 147.48,948.64 v1(175.99,948.64)
NetR10:A_2: R10:A.2 U2:A.14 | length 119.1
  Bottom Layer w10: R10:A.2@320.2,1285.22 R10:A.2@320.2,1282.57 ; R10:A.2@321,1283.38 R10:A.2@320.2,1282.57 ; U2:A.14@334.49,1173.37 334.49,1241.51 320,1256 320,1282.38 R10:A.2@320.2,1282.57
NetR12:A_2: R12:A.2 U2:A.60 | length 122.6
  Top Layer w12: R12:A.2@-84.8,1070.22 -84.8,1051.8 -57,1024 v1(-55,1024)
  Bottom Layer w12: v1(-55,1024) -54.76,1023.76 U2:A.60@7.72,1023.76
NetR13:A_2: R13:A.2 U2:A.6 | length 110.3
  Bottom Layer w10: R13:A.2@128.82,1243.84 162.79,1243.84 177.01,1229.62 U2:A.6@177.01,1173.37
NetR14:A_2: R14:A.2 U2:A.36 | length 126.9
  Top Layer w12: v1(305,674) 306.57,675.57 R14:A.2@306.57,733.84
  Bottom Layer w12: v1(305,674) 314.8,683.8 U2:A.36@314.8,736.36
NetR15:A_1: R15:A.1 S1:A.1 U7:A.1 | length 529.7
  Top Layer w6: S1:A.1@1223.1,1356.4 1223.1,1402.1 1224,1401.2 v1(1224,1401) ; U7:A.1@1430.05,1618 1475,1618 1484,1609 v1(1485,1609)
  Mid-Layer 3 w6: v1(1224,1401) 1248.54,1401 1266.54,1419 1295,1419 v1(1485,1609)
  Bottom Layer w6: R15:A.1@1222,1445 1224,1443 v1(1224,1401) ; v1@1223.1,1410.9 R15:A.1@1223.1,1442.78
NetR16:A_1: R16:A.1 S1:A.2 U7:A.19 | length 571.8
  Top Layer w6: S1:A.2@1273.1,1356.4 1273.1,1402.1 1274,1401.2 v1(1274,1401) ; v1(1615,1603) 1625.43,1592.57 U7:A.19@1665.14,1592.57
  Mid-Layer 3 w6: v1(1274,1401) 1323,1401 1497,1575 1587,1575 v1(1615,1603)
  Bottom Layer w6: v1(1274,1401) 1274,1440.68 R16:A.1@1278.1,1444.78
NetR17_1: R17.1 S4.2 | length 107.8
  Top Layer w6: S4.2@1799.17,1501.93 1801.24,1504 v1(1848,1504)
  Bottom Layer w6: R17.1@1800,1523.62 1819.62,1504 v1(1848,1504) v1@1846.62,1505.38
NetR18_2: R18.2 S4.5 | length 98.1
  Top Layer w6: v1(1902.26,1505.07) 1904.33,1503 S4.5@1948.09,1503
  Bottom Layer w6: v1(1902.26,1505.07) 1927.45,1505.07 R18.2@1946,1523.62
NetR20_1: R20.1 U4.1 | length 69
  Top Layer w6: R20.1@1593.5,1316.5 U4.1@1662.47,1316.5
NetU2:A_40: U2:A.40 U2:A.41 | length 118.3
  Bottom Layer w10: U2:A.41@216.38,736.36 216.38,783.33 222.52,789.47 229.18,789.47 236.06,782.59 U2:A.40@236.06,736.36
NetU2:A_62: U2:A.62 U4:A.2 | length 231
  Top Layer w10: U4:A.2@117.91,998.84 164.2,998.84 v1(164.99,999.64)
  Bottom Layer w10: U2:A.62@7.72,1063.13 61.99,1063.13 125.49,999.64 v1(164.99,999.64)
NetU2:A_63: U2:A.63 U4:A.1 | length 227.2
  Top Layer w10: U4:A.1@117.91,1048.84 164.84,1048.84 v1(165,1049) v1@166,1050
  Bottom Layer w10: U2:A.63@7.72,1082.82 67.18,1082.82 ; 65,1085 67.18,1082.82 ; v1(165,1049) 101,1049 67.18,1082.82 ; v1@166,1050 v1@169,1047
SW_GPIO25: R7.1 S1.5 | length 829.9
  Top Layer w6: v1(1301,226) 1309.46,234.46 S1.5@1360.93,234.46
  Bottom Layer w6: v1(1301,226) 1309,226 1329,246 1552,246 1557,251 1703.14,251 1720.14,268 1928,268 1968,308 R7.1@2033.5,308
SW_GPIO26: R6.1 S2.2 | length 582.3
  Top Layer w6: S2.2@1592.17,234.46 1592.17,264.17 1597,269 v1(1639,269)
  Bottom Layer w6: v1(1639,269) 1665.54,269 1684.54,288 1918,288 1980,350 1980,403.5 R6.1@2033.5,457
SW_GPIO27: R10.1 S2.5 | length 478.2
  Top Layer w6: v1(1692,270) 1732,270 1737.83,264.17 S2.5@1737.83,234.46
  Bottom Layer w6: v1(1692,270) 1708,270 1716,278 1922.14,278 1990,345.86 1990,367 2005,382 R10.1@2033.5,382
XTAL_X1: C18.1 S3.1 Y1.3 | length 390.4
  Top Layer w6: S3.1@1784.17,875.44 1846.44,875.44 1855,884 1855,1011 1843,1023 1825,1023 1812,1010 1805.98,1010 Y1.3@1785.98,990 ; Y1.3@1785.5,989.52 Y1.3@1785.98,990 ; v1@1832,990 Y1.3@1785.98,990
  Bottom Layer w6: C18.1@1785,1008.38 1803.38,990 v1@1832,990
  other v1: 1832,991
XTAL_X2: C17.1 S3.4 Y1.1 | length 379.8
  Top Layer w6: v1(1882.16,1074) Y1.1@1929.03,1074 ; S3.4@1929.83,875.44 1874.56,875.44 1866,884 1866,1010.97 Y1.1@1929.03,1074 ; Y1.1@1931.17,1076.13 Y1.1@1929.03,1074
  Bottom Layer w6: v1(1882.16,1074) 1902.62,1074 C17.1@1921,1055.62
pads on no net: EC1.4 EC1.13 EC1.16 EC1.29 EC1.31 EC1.32 EC1.33 EC1.36 EC1.37 EC1.39 EC1.40 EC1.41 EC1.42 EC1.43 EC1.44 EC1.66 EC1.91 EC1.92 EC1.93 EC1.94 EC1.95 EC1.96 EC1.108 EC1.109 EC1.110 EC1.113 EC1.114 EC1.115 EC1.116 EC1.117 FID1.1 FID2.1 FID3.1 FID4.1 FID5.1 FID6.1 J1.9 J1:A.4 J1:A.ALIGN1 J1:A.ALIGN2 LBL1.0 S5.3 U1.33 U1.34 U2:A.21 U2:A.22 U2:A.23 U2:A.26 U2:A.27 U2:A.29 U2:A.30 U2:A.33 U2:A.34 U2:A.43 U2:A.44 U2:A.45 U2:A.46 U2:A.48 U2:A.52 U2:A.53 U2:A.57 U2:A.58 U2:A.59 U3:A.2 U4:A.7 U7:A.3 U7:A.5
